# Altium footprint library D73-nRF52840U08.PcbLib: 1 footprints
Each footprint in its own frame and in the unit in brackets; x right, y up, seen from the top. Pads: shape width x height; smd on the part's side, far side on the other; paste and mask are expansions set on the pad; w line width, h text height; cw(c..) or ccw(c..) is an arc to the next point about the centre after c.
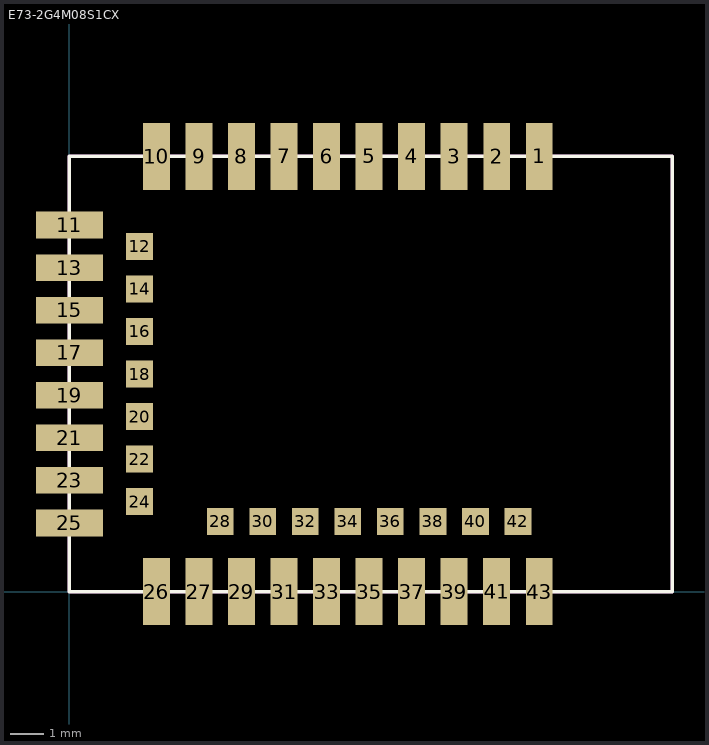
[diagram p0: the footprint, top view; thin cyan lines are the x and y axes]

## E73-2G4M08S1CX [mm]
pads (43):
  rect 0.8x2 smd: 1(14.03,13) 2(12.76,13) 3(11.49,13) 4(10.22,13) 5(8.95,13) 6(7.68,13) 7(6.41,13) 8(5.14,13) 9(3.873,13) 10(2.6,13) 26(2.6,0) 27(3.87,0) 29(5.14,0) 31(6.41,0) 33(7.68,0) 35(8.95,0) 37(10.22,0) 39(11.49,0) 41(12.757,0) 43(14.03,0)
  rect 2x0.8 smd: 11(0,10.945) 13(0,9.675) 15(0,8.405) 17(0,7.135) 19(0,5.865) 21(0,4.595) 23(0,3.325) 25(0,2.055)
  rect 0.8x0.8 smd: 12(2.1,10.31) 14(2.1,9.04) 16(2.1,7.77) 18(2.1,6.5) 20(2.1,5.23) 22(2.1,3.96) 24(2.1,2.69) 28(4.505,2.1) 30(5.775,2.1) 32(7.045,2.1) 34(8.315,2.1) 36(9.585,2.1) 38(10.855,2.1) 40(12.125,2.1) 42(13.395,2.1)
Top Overlay:
  lines w0.1: 0,0 18,0 18,13 0,13 0,0
Keep-Out Layer:
  lines w0.1: 0,0 0,13 18,13 18,0 0,0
